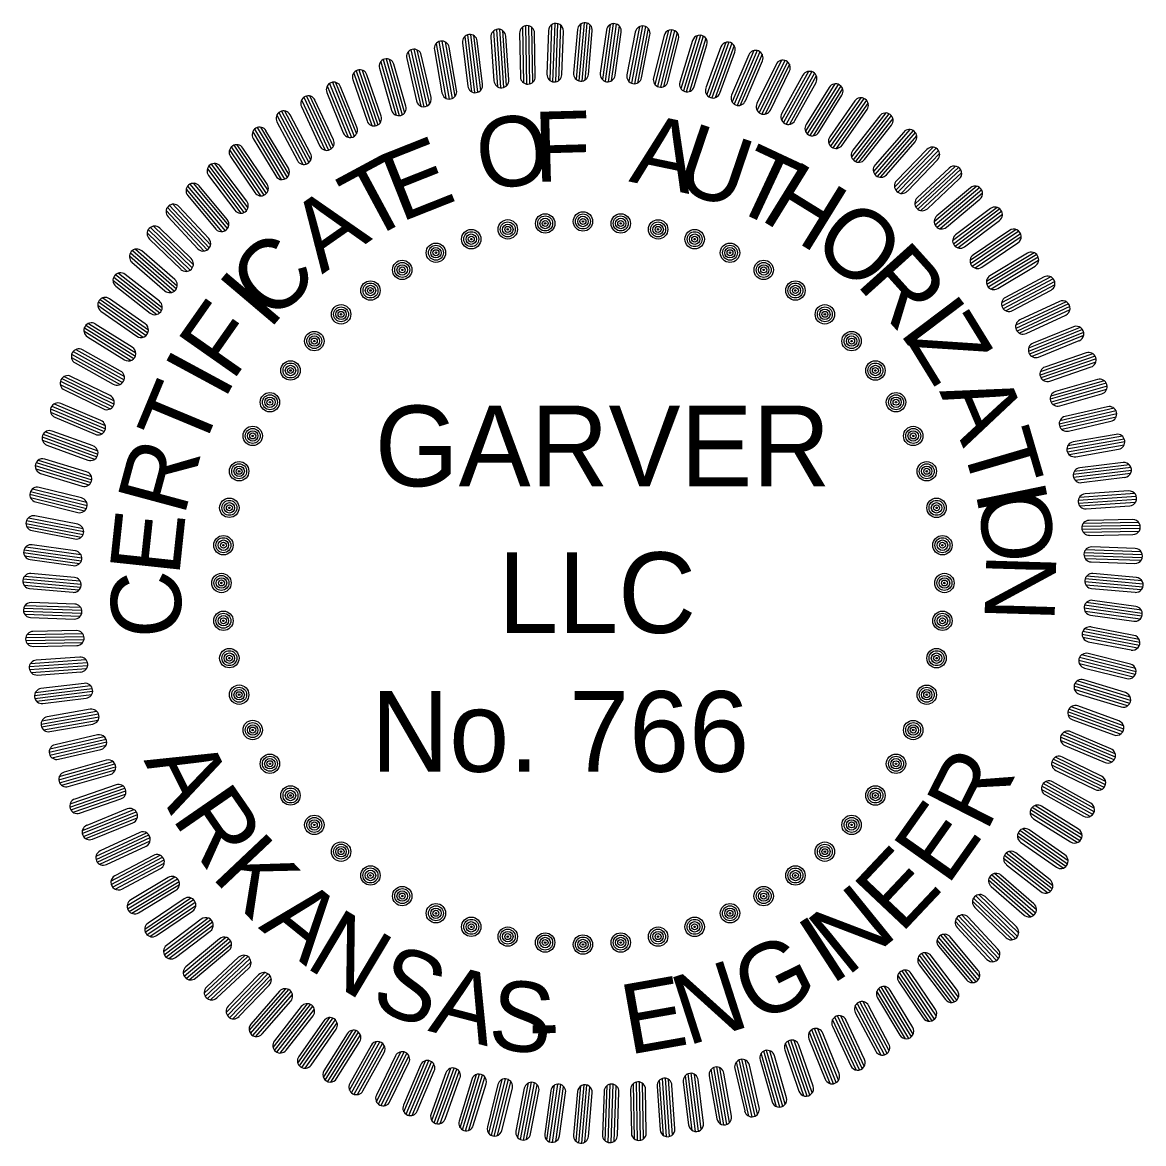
# Model space of a CAD drawing. Extents: x 982240 to 1103002, y 974866 to 1054902.
# Drawn here: x 1087735 to 1094824, y 976296 to 983384 of the extents above; entities that cross this region are included whole.
import ezdxf

# ---------------------------------------------------------------- set-up
doc = ezdxf.new("R2010")
doc.units = 0
doc.layers.add('G-ANNO-TEXT', color=7, linetype='Continuous')

# ---------------------------------------------------------------- blocks, each defined once
blk = doc.blocks.new('SEALDO')
at = {"layer": 'G-ANNO-TEXT'}
for radius in [0.0396, 0.0305, 0.0213, 0.0122, 0.00305]:
    blk.add_circle((1.403, -0.4559), radius, dxfattribs=at)
blk = doc.blocks.new('SEALRI')
at = {"layer": 'G-ANNO-TEXT'}
for p, q in [((-0.0226, 2.2583), (-0.0381, 2.0809)), ((-0.0083, 2.2815), (-0.0281, 2.0555)), ((0.0043, 2.2859), (-0.0164, 2.049)), ((0.0164, 2.2848), (-0.0043, 2.0479)), ((0.0281, 2.2783), (0.0083, 2.0523)), ((0.0226, 2.0756), (0.0381, 2.253))]:
    blk.add_line(p, q, dxfattribs=at)
for centre, start, end in [((0.0078, 2.2556), 355, 175), ((-0.0078, 2.0782), 175, 355)]:
    blk.add_arc(centre, 0.0305, start, end, dxfattribs=at)

msp = doc.modelspace()

# ---------------------------------------------------------------- block references
at = {"layer": 'G-ANNO-TEXT', "xscale": 1549.2929014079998, "yscale": 1549.2929014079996}
for name in ['SEALRI', 'SEALDO']:
    msp.add_blockref(name, (1091279.2, 979839.9), dxfattribs=at)
at = {"layer": 'G-ANNO-TEXT'}
for name, xscale, yscale, rotation in [('SEALRI', 1549.292901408, 1549.292901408, 12), ('SEALRI', 1549.2929014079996, 1549.2929014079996, 9.000000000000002), ('SEALRI', 1549.292901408, 1549.2929014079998, 6.000000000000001), ('SEALRI', 1549.2929014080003, 1549.2929014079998, 3.0000000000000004), ('SEALRI', 1549.2929014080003, 1549.2929014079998, -2.9999999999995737), ('SEALRI', 1549.2929014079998, 1549.2929014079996, -5.9999999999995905), ('SEALRI', 1549.2929014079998, 1549.2929014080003, -8.999999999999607), ('SEALRI', 1549.2929014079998, 1549.2929014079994, -11.999999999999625), ('SEALRI', 1549.292901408, 1549.292901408, 15.000000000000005), ('SEALRI', 1549.292901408, 1549.2929014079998, -14.999999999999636), ('SEALRI', 1549.2929014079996, 1549.2929014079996, 18), ('SEALRI', 1549.2929014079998, 1549.2929014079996, -17.99999999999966), ('SEALRI', 1549.292901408, 1549.292901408, 23.99999999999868), ('SEALRI', 1549.292901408, 1549.292901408, 20.99999999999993), ('SEALRI', 1549.2929014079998, 1549.2929014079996, -20.999999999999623), ('SEALRI', 1549.292901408, 1549.292901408, -23.999999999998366), ('SEALRI', 1549.292901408, 1549.292901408, 26.999999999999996), ('SEALRI', 1549.2929014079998, 1549.292901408, -26.99999999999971), ('SEALRI', 1549.2929014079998, 1549.2929014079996, 30.000000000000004), ('SEALRI', 1549.2929014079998, 1549.2929014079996, -29.999999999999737), ('SEALRI', 1549.292901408, 1549.2929014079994, 33), ('SEALRI', 1549.292901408, 1549.292901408, -32.999999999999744), ('SEALRI', 1549.2929014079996, 1549.2929014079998, 36), ('SEALRI', 1549.2929014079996, 1549.2929014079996, -35.999999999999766), ('SEALRI', 1549.292901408, 1549.292901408, 38.99999999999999), ('SEALRI', 1549.2929014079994, 1549.2929014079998, -38.99999999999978), ('SEALRI', 1549.292901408, 1549.292901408, 41.99999999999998), ('SEALRI', 1549.292901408, 1549.292901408, -41.99999999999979), ('SEALRI', 1549.2929014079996, 1549.2929014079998, 44.99999999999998), ('SEALRI', 1549.292901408, 1549.292901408, -44.9999999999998), ('SEALRI', 1549.2929014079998, 1549.2929014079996, 48), ('SEALRI', 1549.292901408, 1549.292901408, -47.99999999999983), ('SEALDO', 1549.2929014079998, 1549.2929014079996, 113.99999999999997), ('SEALDO', 1549.292901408, 1549.292901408, 107.99999999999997), ('SEALDO', 1549.2929014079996, 1549.2929014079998, 101.99999999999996), ('SEALRI', 1549.292901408, 1549.292901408, 51), ('SEALDO', 1549.2929014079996, 1549.2929014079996, 119.99999999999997), ('SEALDO', 1549.292901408, 1549.2929014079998, 95.99999999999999), ('SEALRI', 1549.292901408, 1549.2929014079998, -50.999999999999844), ('SEALDO', 1549.2929014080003, 1549.2929014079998, 125.99999999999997), ('SEALDO', 1549.2929014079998, 1549.2929014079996, 90), ('SEALRI', 1549.2929014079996, 1549.2929014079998, 54.00000000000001), ('SEALDO', 1549.292901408, 1549.292901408, 131.99999999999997), ('SEALDO', 1549.292901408, 1549.292901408, 83.99999999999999), ('SEALRI', 1549.2929014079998, 1549.292901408, -53.999999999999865), ('SEALDO', 1549.2929014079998, 1549.2929014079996, 138), ('SEALDO', 1549.292901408, 1549.2929014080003, 77.99999999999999), ('SEALRI', 1549.2929014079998, 1549.292901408, 56.999999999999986), ('SEALDO', 1549.2929014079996, 1549.2929014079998, 144), ('SEALDO', 1549.2929014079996, 1549.2929014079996, 72), ('SEALRI', 1549.292901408, 1549.292901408, -56.999999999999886), ('SEALRI', 1549.2929014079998, 1549.2929014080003, 59.999999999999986), ('SEALDO', 1549.2929014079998, 1549.292901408, 150), ('SEALDO', 1549.292901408, 1549.292901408, 66.00000000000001), ('SEALRI', 1549.2929014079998, 1549.2929014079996, -59.99999999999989), ('SEALRI', 1549.2929014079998, 1549.2929014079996, 63), ('SEALRI', 1549.292901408, 1549.292901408, -62.99999999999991), ('SEALDO', 1549.292901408, 1549.292901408, 156.00000000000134), ('SEALDO', 1549.2929014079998, 1549.292901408, 60.00000000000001), ('SEALRI', 1549.292901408, 1549.292901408, 65.99999999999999), ('SEALRI', 1549.292901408, 1549.292901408, -65.99999999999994), ('SEALDO', 1549.2929014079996, 1549.2929014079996, 162.00000000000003), ('SEALDO', 1549.2929014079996, 1549.2929014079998, 54.00000000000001), ('SEALRI', 1549.2929014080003, 1549.292901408, 68.99999999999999), ('SEALRI', 1549.2929014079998, 1549.292901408, -68.99999999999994), ('SEALDO', 1549.2929014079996, 1549.2929014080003, 168.00000000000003), ('SEALDO', 1549.292901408, 1549.292901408, 48.00000000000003), ('SEALRI', 1549.2929014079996, 1549.2929014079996, 72), ('SEALRI', 1549.2929014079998, 1549.2929014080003, -71.99999999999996), ('SEALDO', 1549.292901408, 1549.2929014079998, 174.00000000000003), ('SEALDO', 1549.2929014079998, 1549.2929014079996, 42), ('SEALRI', 1549.292901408, 1549.2929014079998, 75.00000000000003), ('SEALRI', 1549.292901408, 1549.292901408, -74.99999999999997), ('SEALRI', 1549.292901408, 1549.2929014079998, 78.00000000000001), ('SEALDO', 1549.2929014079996, 1549.2929014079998, 36), ('SEALRI', 1549.292901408, 1549.292901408, -78), ('SEALDO', 1549.2929014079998, 1549.2929014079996, -179.99999999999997), ('SEALRI', 1549.2929014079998, 1549.2929014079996, 81), ('SEALRI', 1549.2929014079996, 1549.2929014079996, -81.00000000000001), ('SEALDO', 1549.2929014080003, 1549.2929014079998, -173.99999999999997), ('SEALDO', 1549.2929014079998, 1549.292901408, 29.999999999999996), ('SEALRI', 1549.292901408, 1549.2929014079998, 84.00000000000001), ('SEALRI', 1549.292901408, 1549.2929014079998, -84.00000000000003), ('SEALDO', 1549.2929014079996, 1549.2929014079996, -167.99999999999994), ('SEALDO', 1549.292901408, 1549.292901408, 23.99999999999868), ('SEALRI', 1549.2929014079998, 1549.2929014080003, 87.00000000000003), ('SEALRI', 1549.2929014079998, 1549.292901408, -87.00000000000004), ('SEALDO', 1549.2929014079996, 1549.2929014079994, -161.9999999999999), ('SEALDO', 1549.2929014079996, 1549.2929014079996, 18), ('SEALRI', 1549.2929014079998, 1549.2929014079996, 90.00000000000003), ('SEALRI', 1549.2929014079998, 1549.2929014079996, -90.00000000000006), ('SEALRI', 1549.2929014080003, 1549.2929014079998, 93), ('SEALRI', 1549.2929014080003, 1549.292901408, -93.00000000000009), ('SEALDO', 1549.292901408, 1549.2929014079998, -156.00000000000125), ('SEALDO', 1549.292901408, 1549.292901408, 12), ('SEALRI', 1549.292901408, 1549.292901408, 96.00000000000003), ('SEALRI', 1549.2929014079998, 1549.2929014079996, -96.0000000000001), ('SEALDO', 1549.2929014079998, 1549.2929014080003, -149.99999999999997), ('SEALDO', 1549.292901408, 1549.2929014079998, 6.000000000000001), ('SEALRI', 1549.2929014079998, 1549.292901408, 99.00000000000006), ('SEALRI', 1549.2929014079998, 1549.292901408, -99.00000000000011), ('SEALRI', 1549.2929014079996, 1549.2929014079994, 102.00000000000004), ('SEALDO', 1549.2929014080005, 1549.2929014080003, -143.99999999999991), ('SEALRI', 1549.2929014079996, 1549.2929014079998, -102.00000000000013), ('SEALRI', 1549.292901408, 1549.292901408, 105.00000000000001), ('SEALRI', 1549.292901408, 1549.292901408, -105.00000000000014), ('SEALDO', 1549.292901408, 1549.2929014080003, -137.99999999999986), ('SEALRI', 1549.2929014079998, 1549.2929014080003, 108.00000000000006), ('SEALDO', 1549.2929014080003, 1549.292901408, -6.0000000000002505), ('SEALRI', 1549.292901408, 1549.2929014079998, -108.00000000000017), ('SEALDO', 1549.292901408, 1549.2929014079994, -131.99999999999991), ('SEALRI', 1549.292901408, 1549.2929014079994, 111.00000000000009), ('SEALDO', 1549.2929014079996, 1549.2929014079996, -12.000000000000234), ('SEALRI', 1549.2929014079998, 1549.2929014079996, -111.00000000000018), ('SEALRI', 1549.292901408, 1549.2929014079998, 114.00000000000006), ('SEALDO', 1549.2929014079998, 1549.292901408, -125.9999999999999), ('SEALDO', 1549.2929014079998, 1549.292901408, -18.000000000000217), ('SEALRI', 1549.292901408, 1549.292901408, -114.0000000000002), ('SEALRI', 1549.2929014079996, 1549.2929014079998, 117.00000000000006), ('SEALRI', 1549.2929014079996, 1549.2929014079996, -117.0000000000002), ('SEALDO', 1549.2929014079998, 1549.2929014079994, -119.99999999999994), ('SEALDO', 1549.2929014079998, 1549.2929014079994, -23.999999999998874), ('SEALRI', 1549.2929014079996, 1549.2929014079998, 120.00000000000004), ('SEALRI', 1549.2929014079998, 1549.2929014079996, -120.00000000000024), ('SEALDO', 1549.292901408, 1549.292901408, -113.99999999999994), ('SEALDO', 1549.2929014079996, 1549.2929014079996, -30.00000000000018), ('SEALRI', 1549.2929014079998, 1549.2929014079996, 123.00000000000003), ('SEALRI', 1549.292901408, 1549.292901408, -123.00000000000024), ('SEALDO', 1549.292901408, 1549.2929014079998, -107.99999999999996), ('SEALDO', 1549.2929014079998, 1549.292901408, -36.00000000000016), ('SEALRI', 1549.2929014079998, 1549.292901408, 126.00000000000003), ('SEALRI', 1549.2929014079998, 1549.2929014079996, -126.00000000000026), ('SEALDO', 1549.2929014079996, 1549.2929014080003, -101.99999999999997), ('SEALDO', 1549.2929014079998, 1549.2929014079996, -42.000000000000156), ('SEALRI', 1549.292901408, 1549.292901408, 129.00000000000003), ('SEALRI', 1549.2929014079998, 1549.2929014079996, -129.00000000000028), ('SEALDO', 1549.292901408, 1549.2929014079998, -96), ('SEALDO', 1549.2929014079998, 1549.292901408, -48.000000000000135), ('SEALRI', 1549.2929014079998, 1549.2929014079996, 132), ('SEALDO', 1549.2929014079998, 1549.2929014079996, -90.00000000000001), ('SEALDO', 1549.2929014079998, 1549.2929014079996, -54.000000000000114), ('SEALRI', 1549.2929014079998, 1549.2929014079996, -132.00000000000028), ('SEALDO', 1549.292901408, 1549.2929014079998, -84.00000000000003), ('SEALDO', 1549.2929014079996, 1549.2929014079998, -78.00000000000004), ('SEALDO', 1549.292901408, 1549.2929014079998, -66.00000000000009), ('SEALDO', 1549.2929014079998, 1549.2929014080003, -60.0000000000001), ('SEALRI', 1549.2929014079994, 1549.2929014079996, 135), ('SEALDO', 1549.292901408, 1549.2929014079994, -72.00000000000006), ('SEALRI', 1549.2929014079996, 1549.2929014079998, -135.00000000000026), ('SEALRI', 1549.2929014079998, 1549.2929014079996, 138), ('SEALRI', 1549.2929014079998, 1549.2929014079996, -138.00000000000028), ('SEALRI', 1549.2929014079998, 1549.2929014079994, 140.99999999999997), ('SEALRI', 1549.2929014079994, 1549.2929014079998, -141.0000000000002), ('SEALRI', 1549.2929014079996, 1549.2929014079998, 144), ('SEALRI', 1549.292901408, 1549.2929014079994, -144.00000000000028), ('SEALRI', 1549.292901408, 1549.292901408, 146.99999999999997), ('SEALRI', 1549.292901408, 1549.292901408, -147.00000000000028), ('SEALRI', 1549.2929014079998, 1549.2929014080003, 149.99999999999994), ('SEALRI', 1549.2929014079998, 1549.292901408, -150.00000000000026), ('SEALRI', 1549.292901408, 1549.2929014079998, 152.99999999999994), ('SEALRI', 1549.2929014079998, 1549.292901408, -153.00000000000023), ('SEALRI', 1549.292901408, 1549.2929014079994, 156.00000000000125), ('SEALRI', 1549.2929014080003, 1549.292901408, -156.00000000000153), ('SEALRI', 1549.292901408, 1549.292901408, 159), ('SEALRI', 1549.2929014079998, 1549.292901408, -159.00000000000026), ('SEALRI', 1549.2929014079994, 1549.2929014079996, 161.99999999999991), ('SEALRI', 1549.2929014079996, 1549.2929014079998, 164.99999999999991), ('SEALRI', 1549.2929014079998, 1549.292901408, -165.0000000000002), ('SEALRI', 1549.2929014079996, 1549.2929014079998, -162.00000000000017), ('SEALRI', 1549.2929014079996, 1549.2929014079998, 167.99999999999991), ('SEALRI', 1549.2929014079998, 1549.2929014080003, -168.0000000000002), ('SEALRI', 1549.2929014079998, 1549.2929014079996, 170.9999999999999), ('SEALRI', 1549.2929014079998, 1549.2929014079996, 173.9999999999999), ('SEALRI', 1549.2929014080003, 1549.292901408, 176.9999999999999), ('SEALRI', 1549.2929014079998, 1549.2929014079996, 179.99999999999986), ('SEALRI', 1549.2929014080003, 1549.292901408, -177.00000000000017), ('SEALRI', 1549.2929014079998, 1549.2929014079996, -174.00000000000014), ('SEALRI', 1549.292901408, 1549.292901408, -171.00000000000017)]:
    msp.add_blockref(name, (1091279.2, 979839.9), dxfattribs=dict(at, xscale=xscale, yscale=yscale, rotation=rotation))

# ---------------------------------------------------------------- texts
for s, rotation, p in [('F', 1.61044, (1090973.4, 982375.2)), ('O', 8.2771, (1090637.7, 982317.8)), ('A', 348.2771, (1091565, 982379.1)), ('U', 341.27715, (1091841.9, 982334.8)), ('E', 21.61044, (1090125, 982118.1)), ('T', 334.94377, (1092189.9, 982222.6)), ('T', 28.2771, (1089911.1, 981993.1)), ('H', 328.2771, (1092389.2, 982143.8)), ('A', 34.94377, (1089629.5, 981789.4)), ('O', 319.7874, (1092709.3, 981962)), ('C', 44.38813, (1089315.8, 981477.4)), ('R', 311.99331, (1092999.6, 981730.2)), ('I', 49.74076, (1089293.1, 981432)), ('F', 54.94377, (1089062.6, 981107.6)), ('I', 307.00814, (1093269.8, 981426.7)), ('Z', 301.61044, (1093321.9, 981373.4)), ('I', 61.61044, (1089009.9, 980988.2)), ('T', 67.43139, (1088861.1, 980645.1)), ('A', 292.97516, (1093530.6, 981051.8)), ('T', 286.3085, (1093669.3, 980731.3)), ('R', 74.94377, (1088757.5, 980255.1)), ('I', 281.61044, (1093758, 980419.8)), ('O', 276.48226, (1093775, 980404)), ('E', 83.89849, (1088725.7, 979876.6)), ('N', 268.2771, (1093830.4, 980030.4)), ('C', 91.88416, (1088745.4, 979498.7)), ('A', 296.57465, (1088499.6, 978718.4)), ('R', 63.09594, (1093829.6, 978259)), ('R', 304.61826, (1088674.3, 978353.9)), ('E', 54.73091, (1093583.3, 977919.3)), ('K', 313.3805, (1088923, 977983.4)), ('E', 46.68075, (1093290.2, 977616.9)), ('N', 38.98211, (1092948, 977346.3)), ('A', 321.25836, (1089222.3, 977659.9)), ('N', 329.10994, (1089513.4, 977414.9)), ('I', 32.97899, (1092845.5, 977293.7)), ('G', 26.41319, (1092375.4, 977047)), ('S', 337.62936, (1089922, 977166.1)), ('N', 17.86862, (1091939.4, 976911.6)), ('A', 345.40726, (1090294.6, 977009.6)), ('S', 352.80457, (1090670.2, 976904)), ('E', 10.06947, (1091568.8, 976856.6)), ('-', 0.83848, (1090937.5, 976846.2))]:
    msp.add_text(s, height=442.7, rotation=rotation, dxfattribs=at).set_placement(p)
for s, p in [('GARVER', (1089963.2, 980451.5)), ('LLC', (1090743, 979523.9)), ('No. 766', (1089941.1, 978646.4))]:
    msp.add_text(s, height=509.99, dxfattribs=at).set_placement(p)

doc.saveas('drawing.dxf')
